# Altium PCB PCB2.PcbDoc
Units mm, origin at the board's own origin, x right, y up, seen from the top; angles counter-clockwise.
Board outline 127 x 101.6 mm, 4 copper layers (Top Layer, Internal Plane 1, Internal Plane 2, Bottom Layer); 12 components, 8 nets, 22 pads, 0 vias.
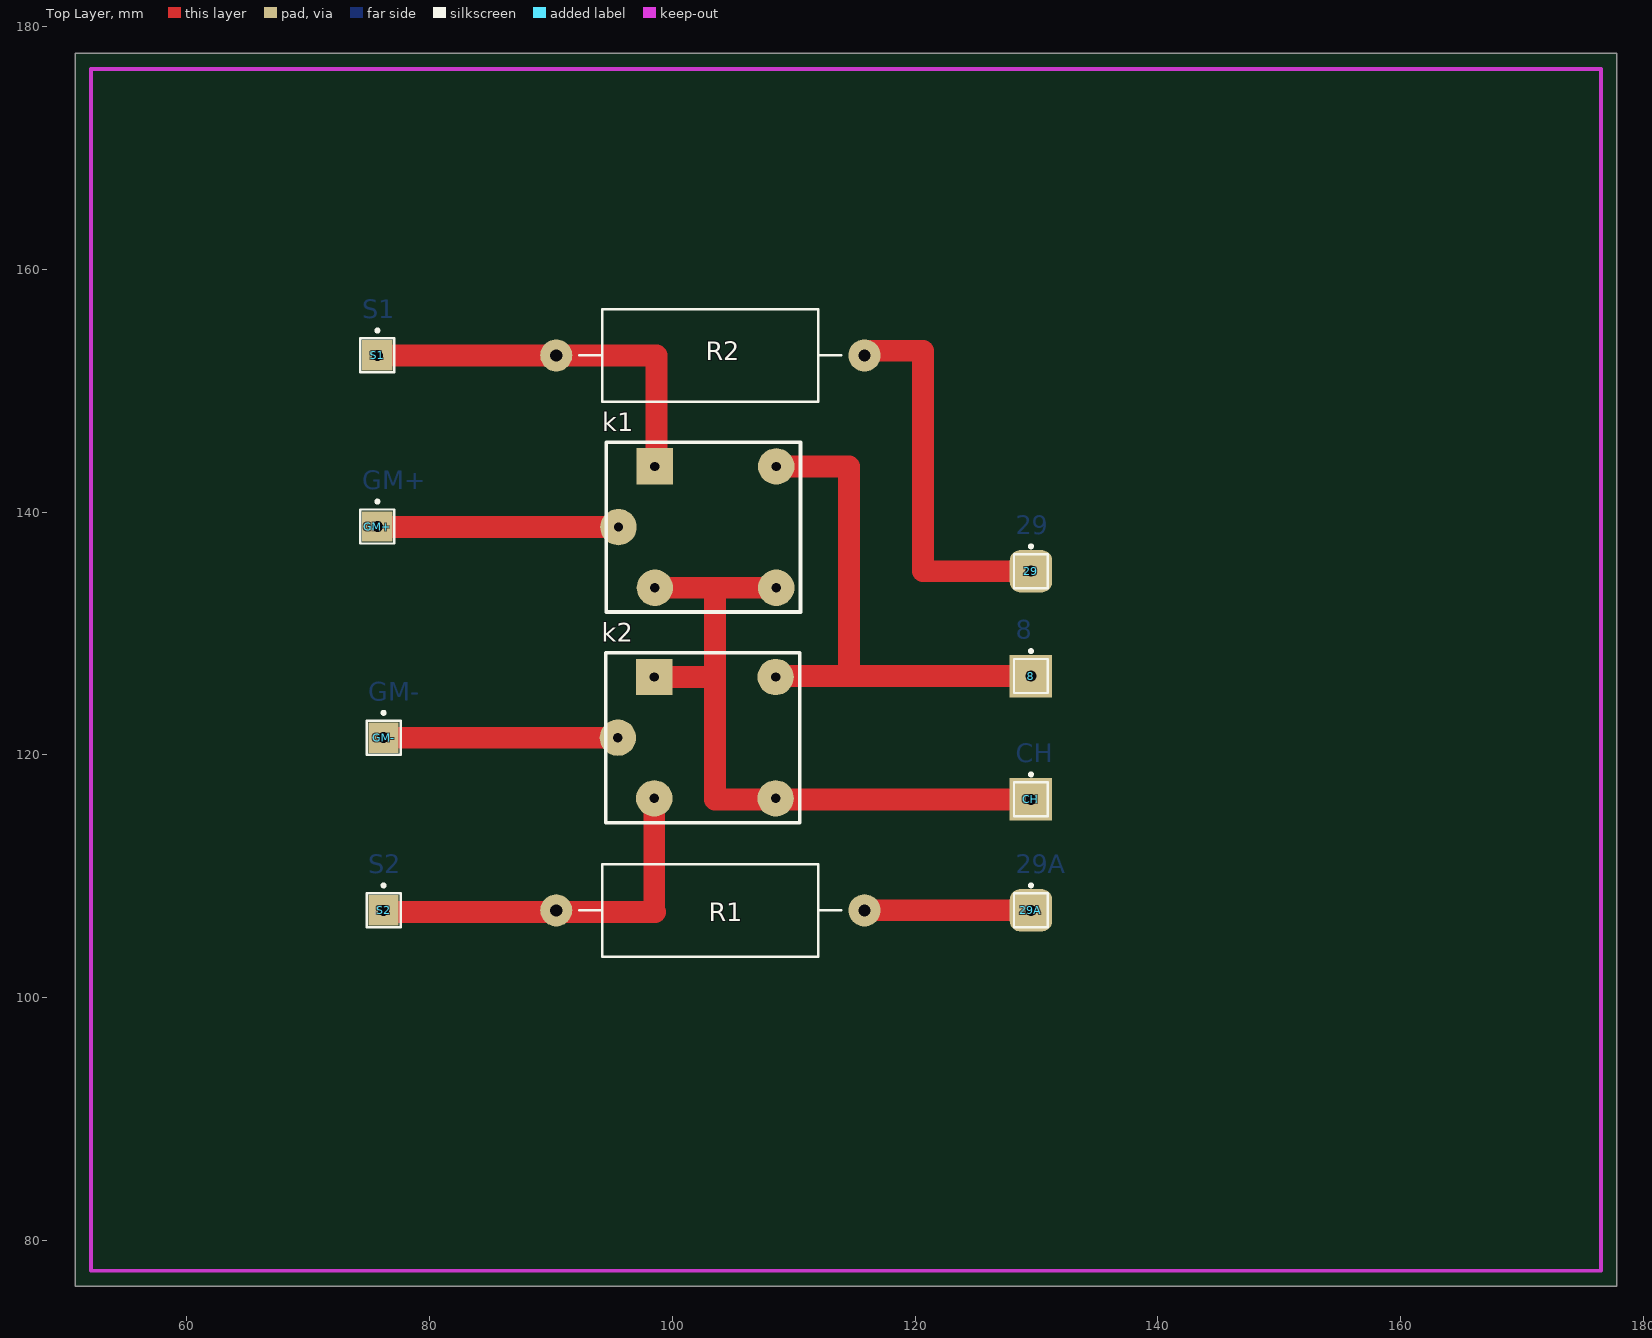
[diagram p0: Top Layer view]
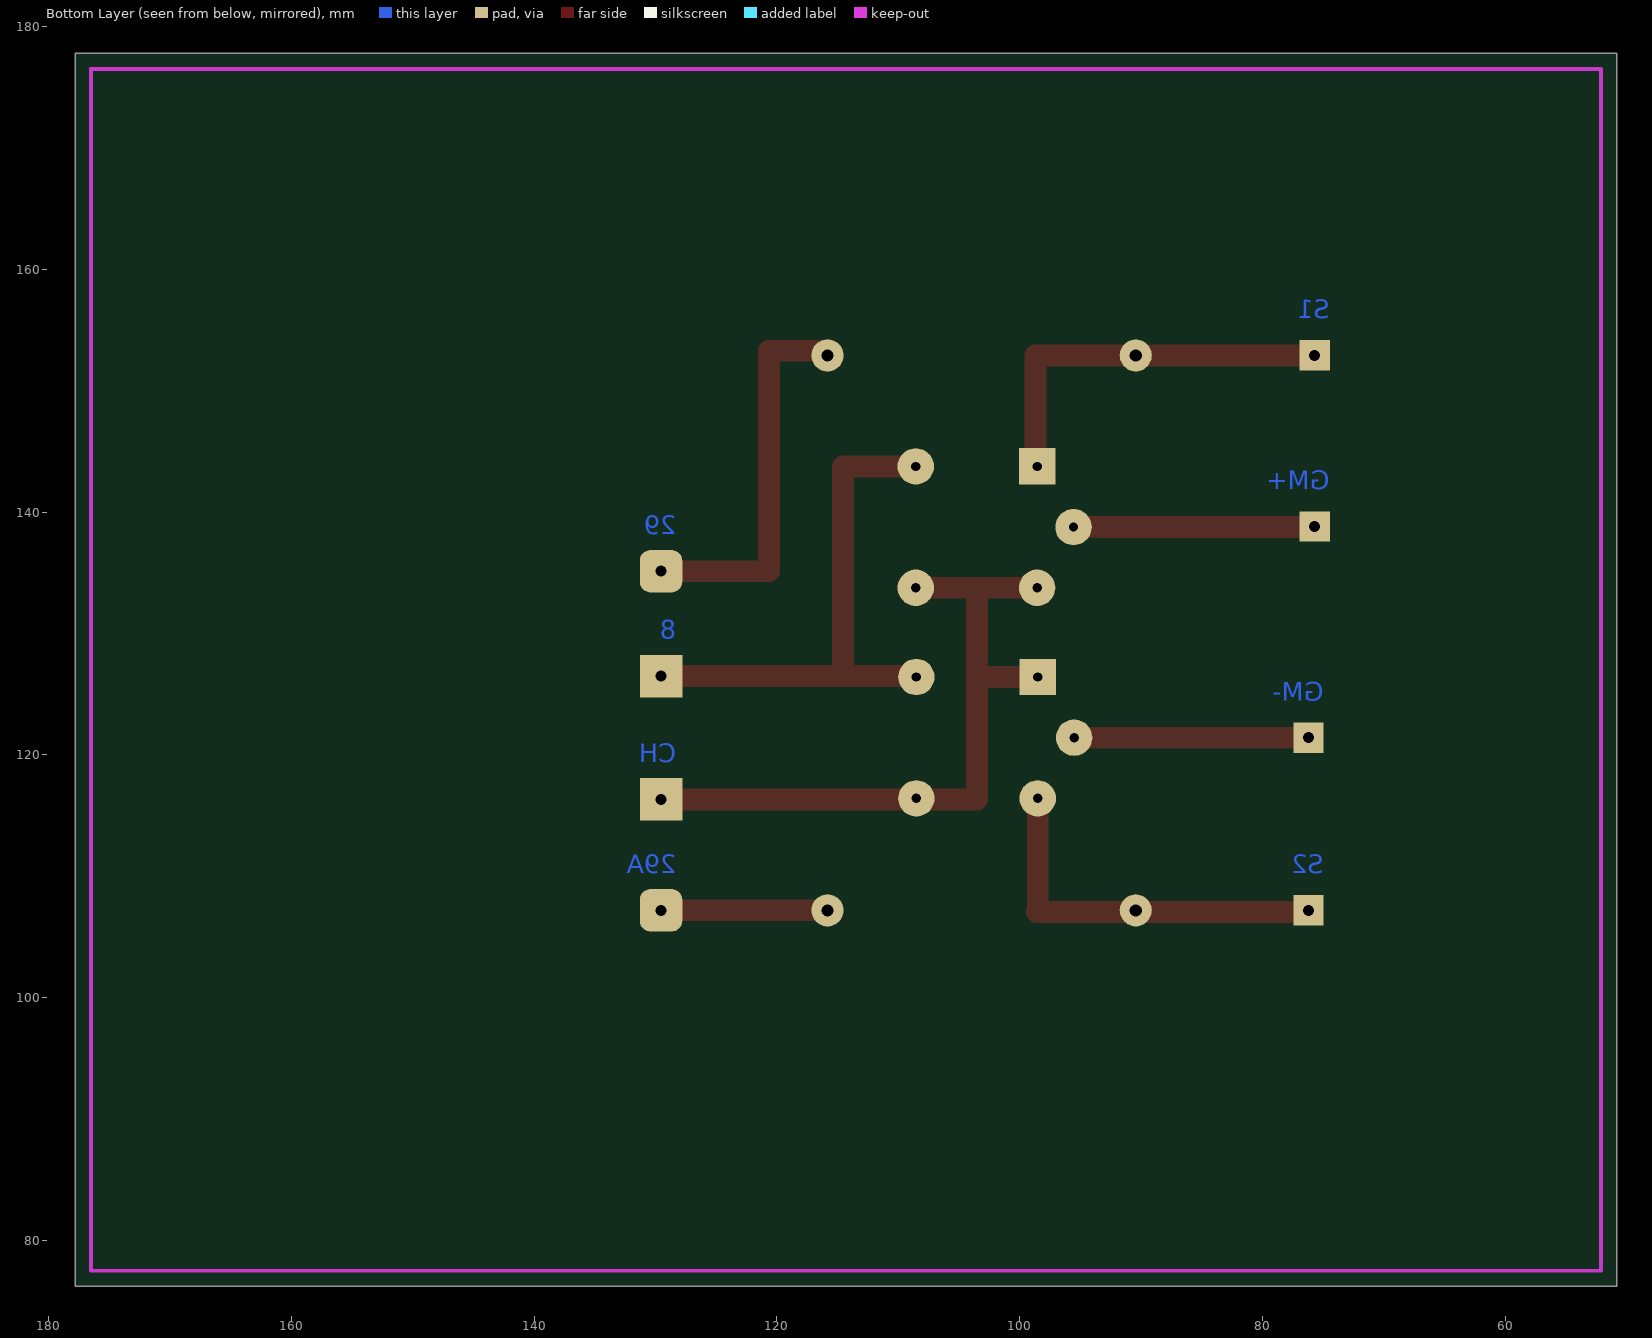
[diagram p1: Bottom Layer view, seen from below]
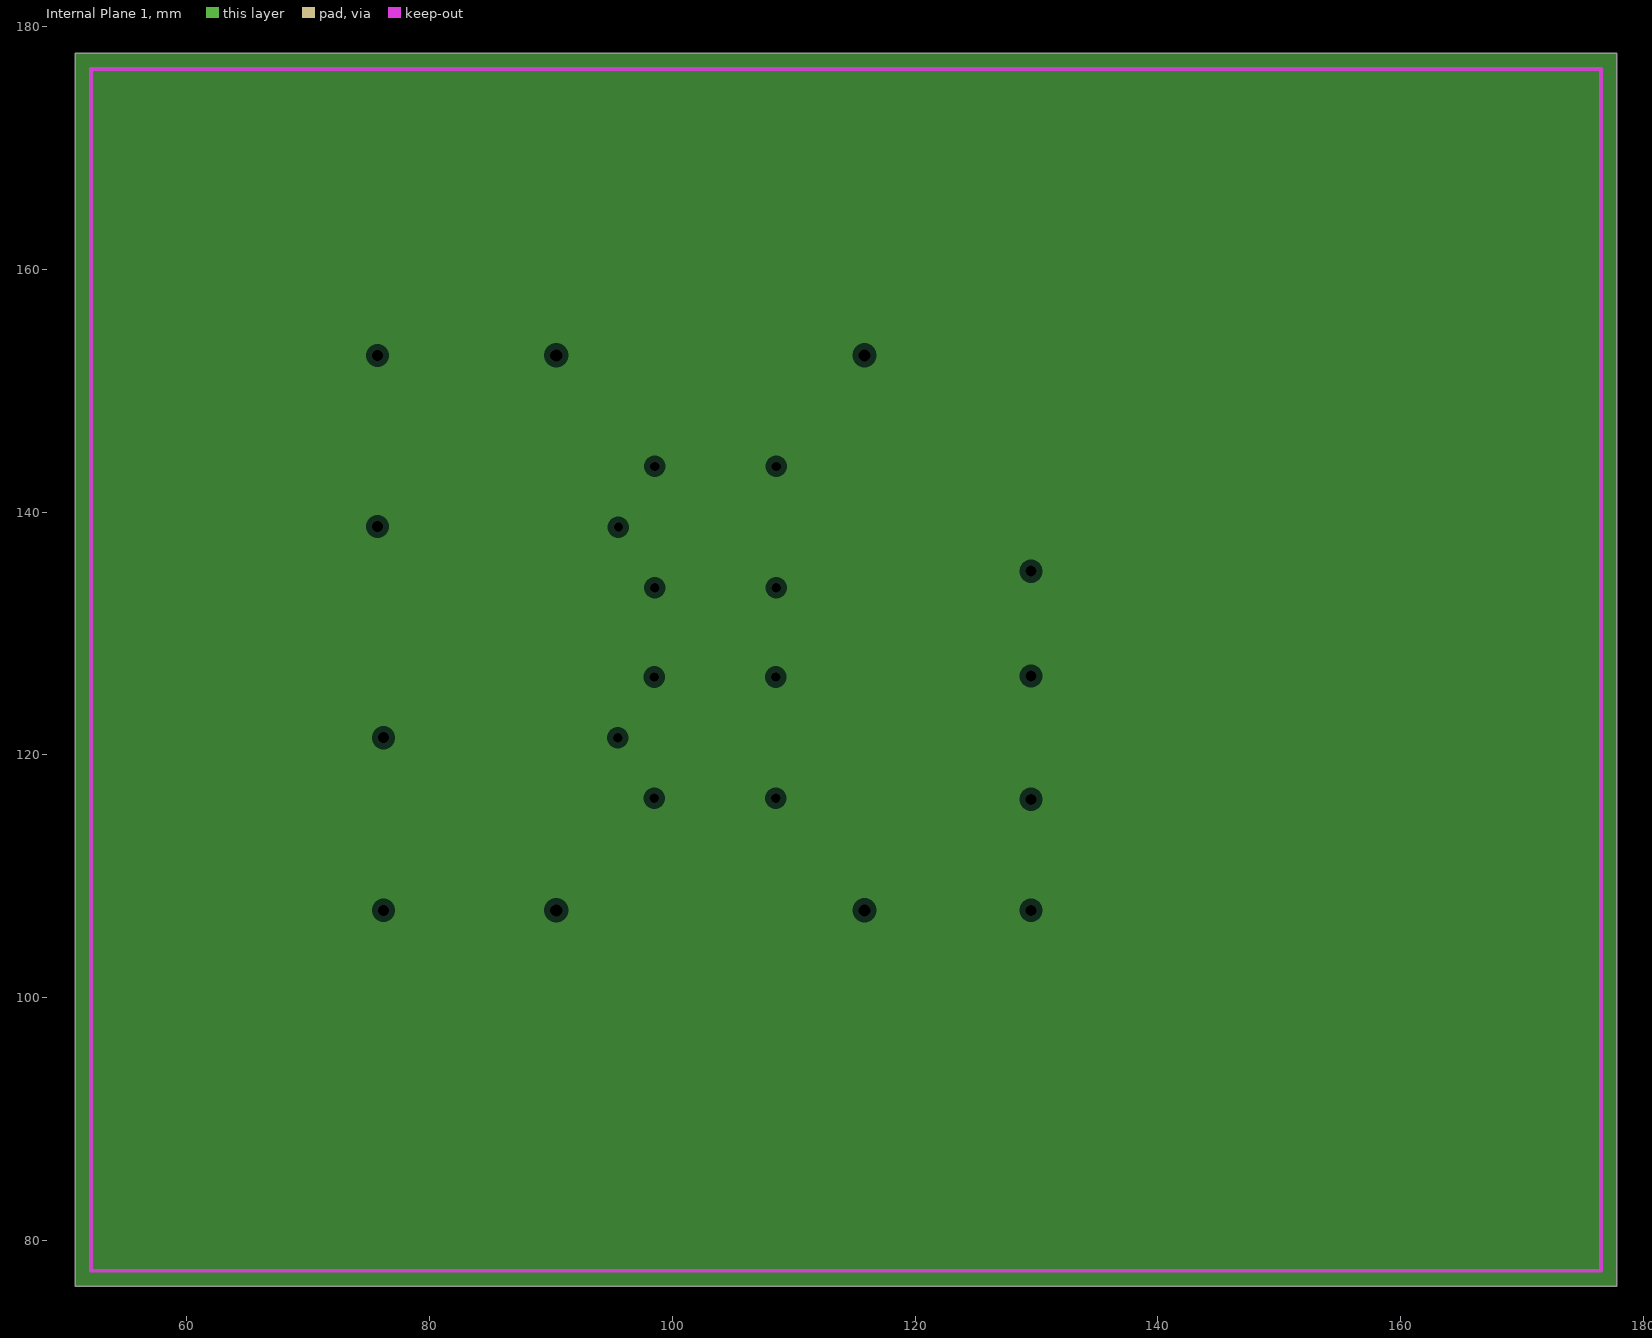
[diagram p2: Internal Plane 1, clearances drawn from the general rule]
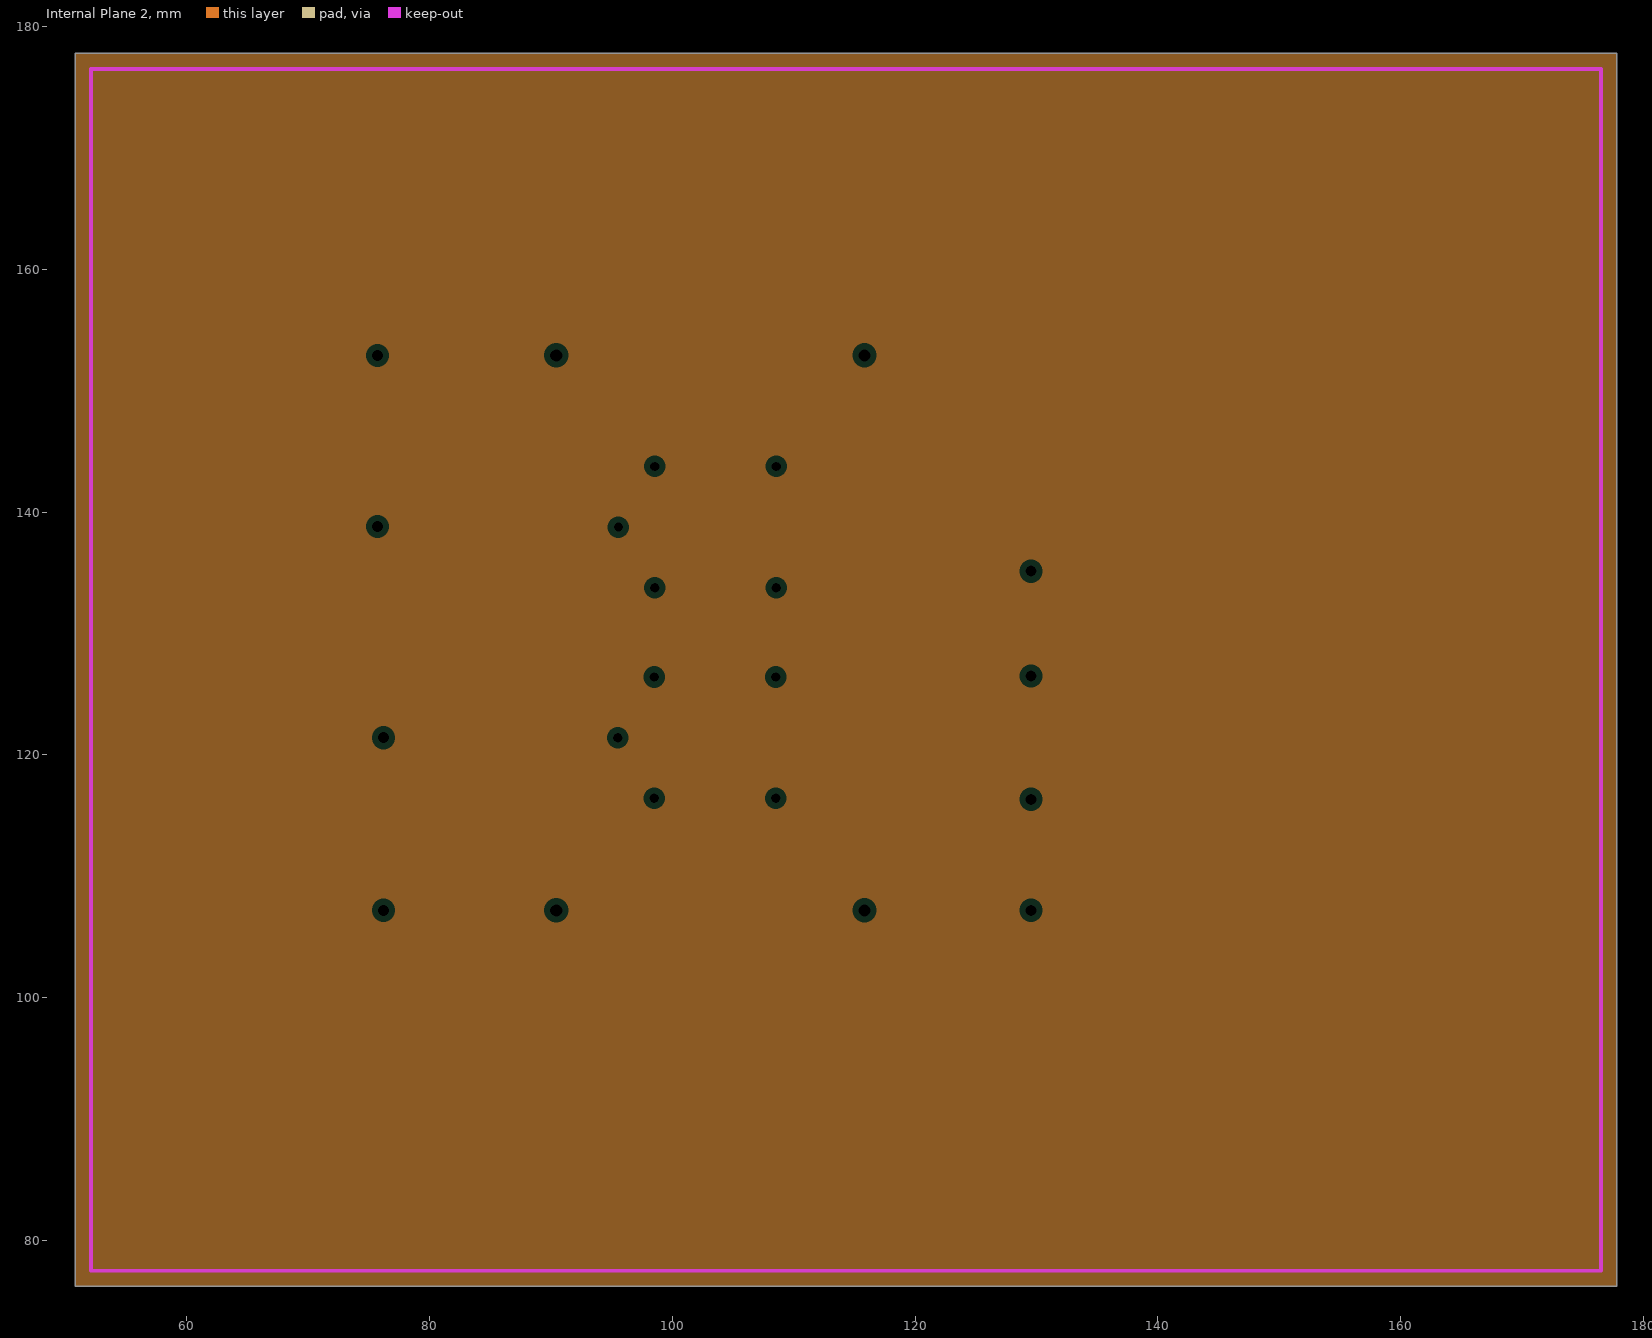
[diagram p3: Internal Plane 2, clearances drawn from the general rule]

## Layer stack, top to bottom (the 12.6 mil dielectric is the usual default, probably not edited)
Top Layer: signal copper 0.0356
Dielectric: dielectric 0.32, FR-4, Dk 4.8
Internal Plane 1: plane copper 0.0356
Dielectric: dielectric 0.32, FR-4, Dk 4.8
Internal Plane 2: plane copper 0.0356
Dielectric: dielectric 0.32, FR-4, Dk 4.8
Bottom Layer: signal copper 0.0356

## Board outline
50.8,76.2 177.8,76.2 177.8,177.8 50.8,177.8

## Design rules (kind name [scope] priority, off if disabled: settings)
Clearance [All] p1: gap=0.6
PlaneClearance [All] p1: clearance=0.508
PlaneConnect [All] p1: planeconnectstyle=Relief reliefexpansion=0.508 reliefentries=4 reliefconductorwidth=0.254 reliefairgap=0.254
PolygonConnect [All] p1: connectstyle=Relief reliefconductorwidth=0.254 reliefentries=4 polygonreliefangle="90 Angle"
RoomDefinition Sheet1 [InComponentClass('Sheet1')] p1: confinementstyle=ConfineIn formatcopy=TRUE lockcomponents=FALSE outline 178.943,77.724 196.088,77.724 196.088,94.996 178.943,94.996
RoutingVias [All] p1: holewidth=0.8 width=2.6 viastyle="Through Hole" minholewidth=0.711 minwidth=1.27 maxholewidth=0.711 maxwidth=1.27
SolderMaskExpansion [All] p1: expansion=0.102
TestPointUsage [All] p1: valid=0 allowmultiple=FALSE
Testpoint [All] p1: side=15 testpointundercomponent=TRUE minsize=1.016 maxsize=2.54 preferedsize=1.524 minholesize=0 maxholesize=1.016 preferedholesize=0.813 testpointgrid=0.025 style=1023 order=0123456789
Width [All] p1: maxlimit=3.8 minlimit=0.8 preferedwidth=0.8 toplayer_prefwidth=1.5 bottomlayer_maxwidth=0.8 minimp=50.000000 maximp=50.000000 favimp=50.000000
17 further rules are at their usual default settings.

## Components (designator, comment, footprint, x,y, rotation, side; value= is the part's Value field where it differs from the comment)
8 "8" PIN1#1 129.54,126.492 r0 top (schematic designator P3)
29 "29A" PIN1#2 129.54,135.128 r0 top (schematic designator P1)
29A "29" PIN1#2 129.54,107.188 r0 top (schematic designator P2)
CH "CH" PIN1#1 129.54,116.332 r0 top (schematic designator P4)
GM+ "Motor" PIN1#3 75.692,138.811 r0 top (schematic designator P5)
GM- "Motor" PIN1#3 76.2,121.412 r0 top (schematic designator P6)
k1 "Component_1" PCBComponent_1 91.552,130.764 r0 top
k2 "Component_1" PCBComponent_1 91.504,113.412 r0 top
R1 "Res2" AXIAL-1.0 103.124,107.188 r180 top
R2 "Res2" AXIAL-1.0 103.124,152.908 r180 top
S1 "S1" PIN1#3 75.692,152.908 r0 top (schematic designator P7)
S2 "S2" PIN1#3 76.2,107.188 r0 top (schematic designator P8)

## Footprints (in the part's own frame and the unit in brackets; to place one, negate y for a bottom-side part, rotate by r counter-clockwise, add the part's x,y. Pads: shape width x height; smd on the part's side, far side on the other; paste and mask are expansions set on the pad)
AXIAL-1.0 [mm] "Adjustable Magnetic-Core Inductor; 2 Leads"
  round 2.65 hole 1: 1(-12.7,0) 2(12.7,0)
  silkscreen extent -10.79,-3.81 10.79,3.81
PCBComponent_1 [mm]
  rect 3x3 hole 0.762: 1(7,13)
  round 3 hole 0.762: 2(7,3) 3(4,8) 4(17,13) 5(17,3)
  silkscreen extent 3,1 19,15, body extent 3,1 19,15, height 12.5
PIN1#1 [mm] "Connector; Plug"
  rect 3.5x3.5 hole 0.9: 1(0,0)
  silkscreen extent -1.4,-1.4 1.4,2.17
PIN1#2 [mm] "Connector; Plug"
  rrect50% 3.5x3.5 hole 0.9: 1(0,0)
  silkscreen extent -1.4,-1.4 1.4,2.17
PIN1#3 [mm] "Connector; Plug"
  rect 2.5x2.5 hole 0.9: 1(0,0)
  silkscreen extent -1.4,-1.4 1.4,2.17

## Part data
8 29 29A CH GM+ GM- S1 S2: library part Plug, "Plug"
R1 R2: "Resistor"

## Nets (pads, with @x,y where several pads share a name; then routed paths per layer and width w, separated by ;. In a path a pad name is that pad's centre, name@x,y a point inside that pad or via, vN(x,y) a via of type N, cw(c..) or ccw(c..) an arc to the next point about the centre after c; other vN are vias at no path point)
GND: CH.1 k1.2 k1.5 k2.1 k2.5 | length 58.5
  Top Layer w1.8: k2.1@98.552,126.46 k2.1 103.505,126.412 ; k1.2 103.505,133.764 ; k1.5 103.505,133.764 ; CH.1 108.504,116.332 103.505,116.332 103.505,126.412 ; 103.505,126.412 103.505,133.764
Netk1_1: k1.1 R2.2 S1.1 | length 32.2
  Top Layer w1.8: S1.1 R2.2 98.679,152.908 98.679,143.891 k1.1
Netk1_3: GM+.1 k1.3 | length 19.9
  Top Layer w1.8: GM+.1 75.739,138.764 k1.3
Netk1_4: 8.1 k1.4 k2.4 | length 44.7
  Top Layer w0.8: 8.1 8.1@129.921,126.492
  Top Layer w1.8: k2.4 108.584,126.492 114.554,126.492 ; k1.4 114.554,143.764 114.554,126.492 ; 8.1 114.554,126.492
Netk2_2: k2.2 R1.2 S2.1 | length 31.9
  Top Layer w1.8: S2.1 76.326,107.062 90.424,107.062 98.298,107.062 ; k2.2 98.504,107.268 98.298,107.062 ; 98.584,107.062 98.298,107.062
Netk2_3: GM-.1 k2.3 | length 19.3
  Top Layer w1.8: GM-.1 k2.3
NetP1_1: 29.1 R2.1 | length 32
  Top Layer w1.8: R2.1 116.205,153.289 120.65,153.289 120.65,135.128 29.1
NetP2_1: 29A.1 R1.1 | length 13.2
  Top Layer w1.8: R1.1@116.332,107.188 29A.1

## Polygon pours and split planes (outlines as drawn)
no net on Internal Plane 1 (split plane): 177.8,76.2 50.8,76.2 50.8,177.8 177.8,177.8
no net on Internal Plane 2 (split plane): 177.8,76.2 50.8,76.2 50.8,177.8 177.8,177.8

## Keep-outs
Keep-Out Layer:
  lines w0.3: 52.1,77.5 52.1,176.5 176.5,176.5 176.5,77.5 52.1,77.5

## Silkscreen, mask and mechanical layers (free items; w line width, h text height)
Drill Drawing:
  text ".LEGEND" at 182.88,81.28 h1.52
  text "Drill Drawing." at 182.88,78.74 h1.52

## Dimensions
52.1,77.5 to 52.1,176.5 on Mechanical 1
52.1,77.5 to 176.5,77.5 on Mechanical 1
